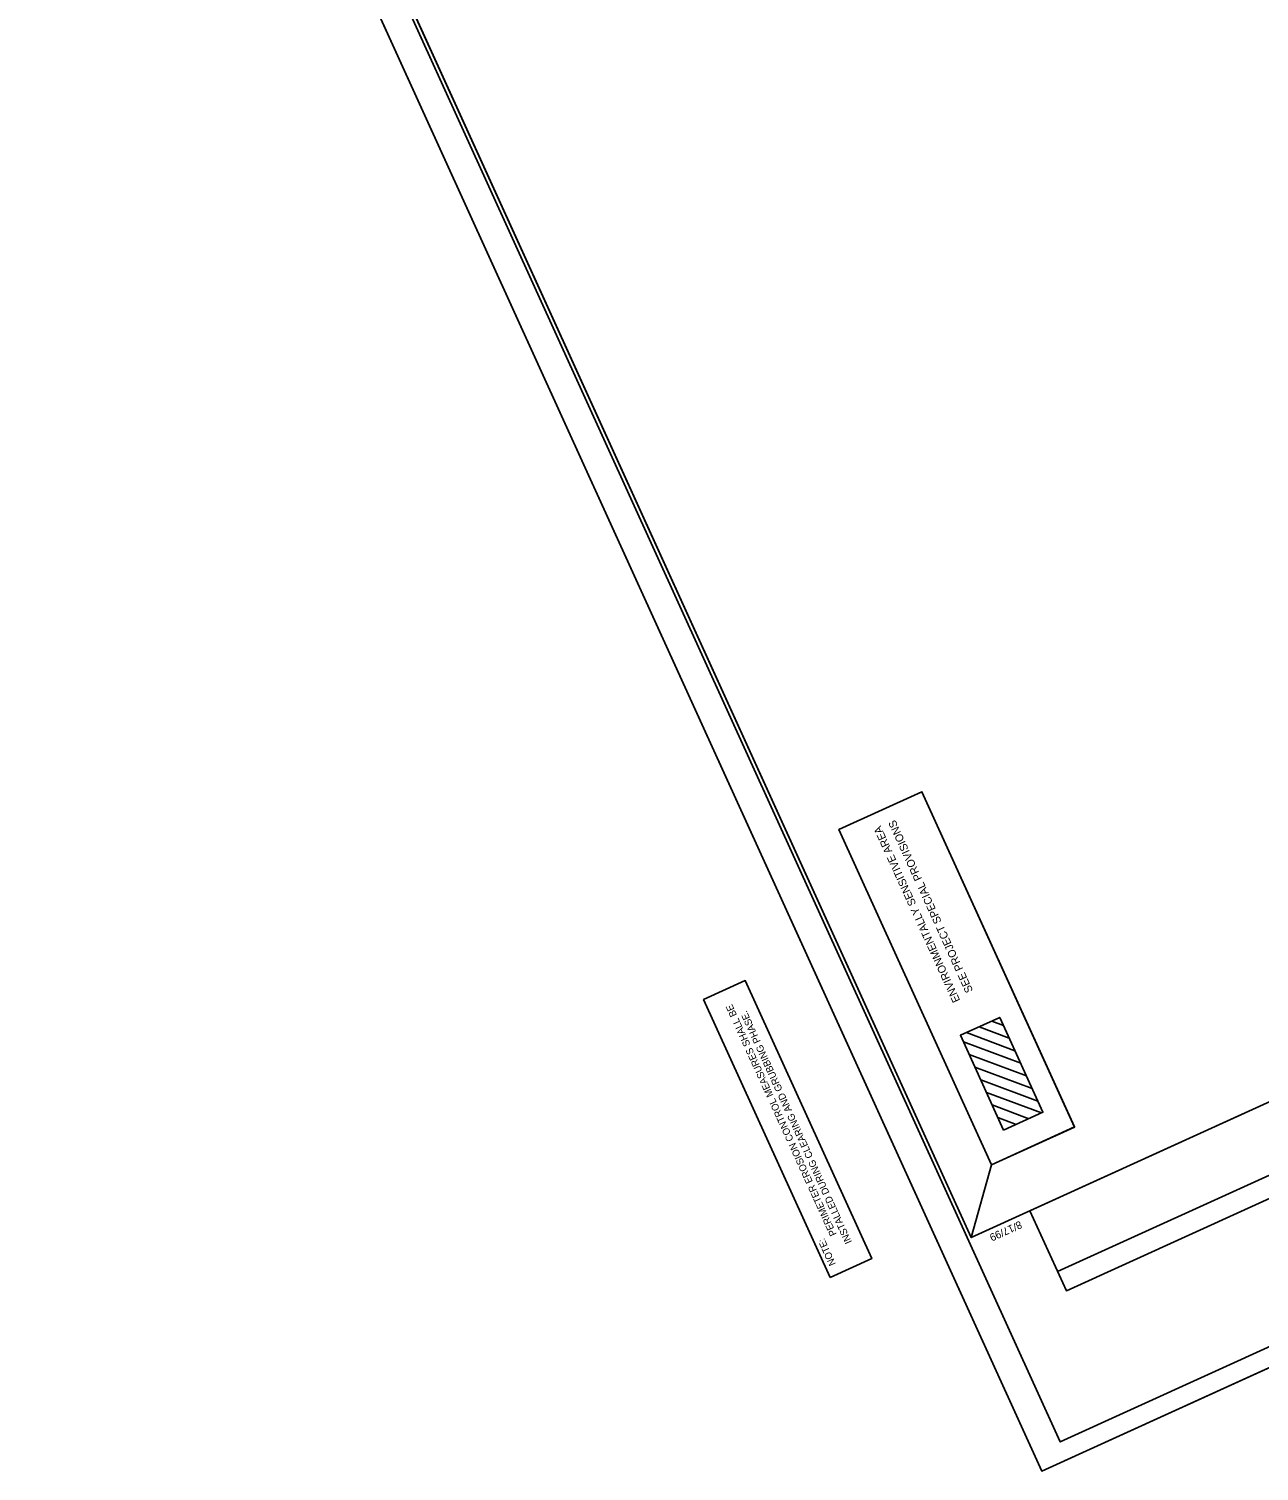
# Model space of a CAD drawing. Extents: x 2097293 to 2098987, y 683915 to 685901.
# Drawn here: x 2097293 to 2098140, y 683915 to 684908 of the extents above; entities that cross this region are included whole.
import ezdxf

# ---------------------------------------------------------------- set-up
doc = ezdxf.new("R2010")
doc.units = 0
for name, color, linetype in [('Construction Sheet Number Note CG CELL', 7, 'Continuous'), ('Environmentally Sensitive Area Note CELL', 7, 'Continuous'), ('Scratch_Level_6', 7, 'Continuous'), ('Sheet Block Revision CELL', 7, 'Continuous'), ('Sheet Cutting Line CELL', 7, 'Continuous'), ('Sheet Layout Plan Border', 7, 'Continuous'), ('Sheet Plan CELL', 7, 'Continuous'), ('Sheet Plot Border Inside CELL', 7, 'Continuous'), ('Sheet Plot Border Outside CELL', 7, 'Continuous')]:
    doc.layers.add(name, color=color, linetype=linetype)

msp = doc.modelspace()

# ---------------------------------------------------------------- linework, layer by layer
at = {"layer": 'Construction Sheet Number Note CG CELL'}
msp.add_lwpolyline([(2097844.35, 684048.26), (2097757.27, 684239.66), (2097786.02, 684252.75), (2097873.11, 684061.35)], close=True, dxfattribs=at)
at = {"layer": 'Environmentally Sensitive Area Note CELL'}
for p, q in [((2097967.7, 684213.18), (2097946.99, 684220.98)), ((2097963.74, 684221.87), (2097955.67, 684224.93)), ((2097971.64, 684204.51), (2097938.27, 684217.01)), ((2097975.59, 684195.82), (2097936.22, 684210.54)), ((2097979.54, 684187.14), (2097940.17, 684201.85)), ((2097983.5, 684178.46), (2097944.12, 684193.18)), ((2097987.45, 684169.77), (2097948.07, 684184.49)), ((2097989.81, 684161.65), (2097952.02, 684175.8)), ((2097981.08, 684157.68), (2097955.97, 684167.12)), ((2097972.4, 684153.73), (2097959.93, 684158.44))]:
    msp.add_line(p, q, dxfattribs=at)
for points in [[(2097955.51, 684125.97), (2097850.47, 684356.82), (2097907.56, 684382.81), (2098012.65, 684151.97)], [(2097963.84, 684149.84), (2097934.13, 684215.13), (2097961.2, 684227.44), (2097990.91, 684162.15)]]:
    msp.add_lwpolyline(points, close=True, dxfattribs=at)
at = {"layer": 'Scratch_Level_6'}
msp.add_line((2097955.51, 684125.97), (2097941.56, 684075.89), dxfattribs=at)
msp.add_lwpolyline([(2097955.51, 684125.97), (2097850.47, 684356.83), (2097907.56, 684382.81), (2098012.61, 684151.96)], close=True, dxfattribs=at)
at = {"layer": 'Sheet Block Revision CELL'}
msp.add_line((2098720.62, 684379.88), (2098000.99, 684052.41), dxfattribs=at)
msp.add_lwpolyline([(2098726.67, 684366.65), (2098007.02, 684039.18), (2097981.92, 684094.27), (2098701.57, 684421.74)], close=True, dxfattribs=at)
at = {"layer": 'Sheet Cutting Line CELL'}
for p, q in [((2097292.78, 685447.36), (2097990.05, 683915.04)), ((2097990.05, 683915.04), (2098986.71, 684368.56))]:
    msp.add_line(p, q, dxfattribs=at)
at = {"layer": 'Sheet Layout Plan Border'}
for points in [[(2098897.26, 684510.8), (2097941.56, 684075.89), (2097486.05, 685076.91), (2097476.37, 685098.19), (2097403.15, 685259.11), (2097618.23, 685357), (2097567.61, 685468.23), (2098309.25, 685803.01)], [(2098897.26, 684510.8), (2097941.56, 684075.89), (2097486.05, 685076.91), (2097476.38, 685098.16), (2097403.15, 685259.11), (2097618.23, 685357), (2097567.61, 685468.23), (2098309.25, 685803.01)]]:
    msp.add_lwpolyline(points, close=True, dxfattribs=at)
at = {"layer": 'Sheet Plan CELL'}
msp.add_line((2097941.56, 684075.89), (2097941.56, 684075.89), dxfattribs=at)
for points in [[(2097320.28, 685441.22), (2097941.56, 684075.89), (2098897.27, 684510.77), (2098276, 685876.08)], [(2098897.27, 684510.77), (2097941.59, 684075.88), (2097403.14, 685259.11), (2097539.72, 685321.27), (2097456.88, 685503.35), (2098276, 685876.08)]]:
    msp.add_lwpolyline(points, close=True, dxfattribs=at)
at = {"layer": 'Sheet Plot Border Inside CELL'}
msp.add_lwpolyline([(2098963.13, 684372.11), (2098273.1, 685888.48), (2097312.85, 685451.54), (2098002.87, 683935.16)], close=True, dxfattribs=at)
at = {"layer": 'Sheet Plot Border Outside CELL'}
msp.add_lwpolyline([(2098986.71, 684368.56), (2098289.45, 685900.88), (2097292.78, 685447.36), (2097990.05, 683915.04)], close=True, dxfattribs=at)

# ---------------------------------------------------------------- texts
at = {"layer": 'Construction Sheet Number Note CG CELL'}
for s, p in [('PERIMETER EROSION CONTROL MEASURES SHALL BE', (2097849.03, 684078.19)), ('   INSTALLED DURING CLEARING AND GRUBBING PHASE.', (2097861.74, 684067.87)), ('NOTE:', (2097848.49, 684057.73))]:
    msp.add_text(s, height=4.86, rotation=114.46742, dxfattribs=at).set_placement(p)
at = {"layer": 'Environmentally Sensitive Area Note CELL'}
for s, p in [('SEE PROJECT SPECIAL PROVISIONS', (2097942.88, 684245.8)), ('ENVIRONMENTALLY SENSITIVE AREA', (2097934.03, 684239.12))]:
    msp.add_text(s, height=5.4, rotation=114.47302, dxfattribs=at).set_placement(p)
at = {"layer": 'Sheet Plan CELL'}
msp.add_text('8/17/99', height=5.25, rotation=204.46742, dxfattribs=at).set_placement((2097974.96, 684087.54))

doc.saveas('drawing.dxf')
